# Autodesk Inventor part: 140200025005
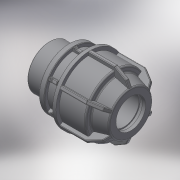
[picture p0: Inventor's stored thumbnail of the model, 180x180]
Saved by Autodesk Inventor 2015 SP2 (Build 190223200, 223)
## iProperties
Created: 2017-08
Part Number: 140200025005
Material: Generic
Description: PLASSON L.14 MALE ADAPTOR (SILVER) 25-1/2''
Document SubType Name: Modeling
Designer: KIM
Density: 1 g/cm^3
Appearance: Default
Author: KIM
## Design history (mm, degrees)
derived "140200.ipt"
feature "Solid1::140200.ipt"
tag "TaggingFeature1"
body "Solid1"
other parameters: "d1" = 25, "d2" = 54, "d4" = 15 deg, "d5" = 35.64, "d6" = 11.7612, "d16" = 25.5, "d17" = 2.7, "d18" = 75, "d19" = 5.1, "d21" = 5.1, "d22" = 29.337, "d24" = 2.7, "d25" = 45, "d26" = 37.5, "d27" = 2.7, "d28" = 135 deg, "d29" = 1.62, "d31" = 1.25, "d44" = 0.5, "d45" = 0.75, "d46" = 150 deg, "d49" = 2.5, "d50" = 0, "d51" = 1.5, "d52" = 1, "d53" = 45 deg, "d54" = 21, "d55" = 8.4, "d56" = 2.5, "d57" = 0, "d58" = 0.75, "d59" = 0.5, "d61" = 360 deg, "d63" = 20.955, "d64" = 15, "d65" = 17, "d66" = 31.4325, "d_" = 25, "R_" = 20.955, "H_" = 75, "l_" = 54, "l_2" = 17
